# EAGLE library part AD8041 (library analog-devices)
160 MHz Rail-to-Rail Amplifier with Disable Source: http://www.analog.com/static/imported-files/data_sheets/AD8041.pdf
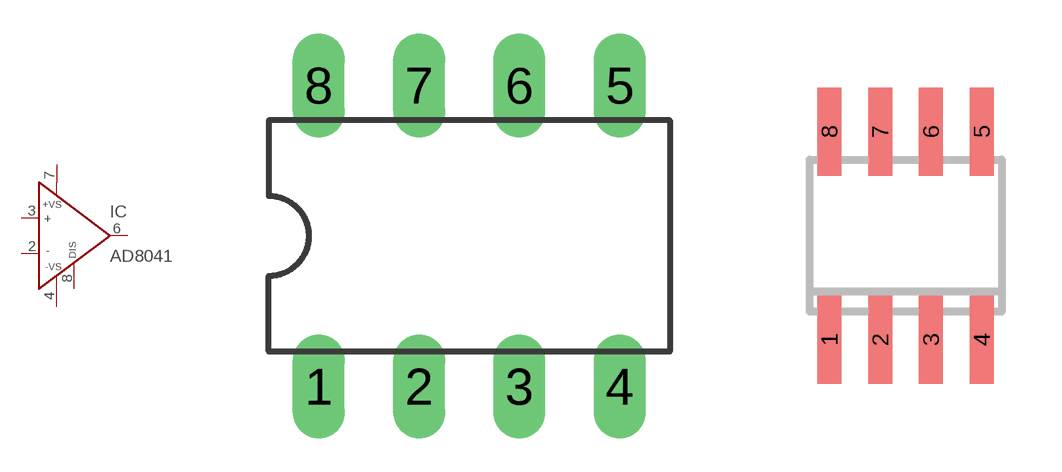
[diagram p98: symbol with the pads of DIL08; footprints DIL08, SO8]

Designator prefix IC

## AD8041N (MPN: AD8041ANZ; OC_FARNELL: 1438577; OC_NEWARK: 15P0923)  [DIL08]
2  IN-  in
3  IN+  in
4  -VS  in
6  OUT  out
7  +VS  in
8  DISABLE  pas

## AD8041R (MF: ALTERA CORPORATION; MPN: AD8041ARZ; OC_FARNELL: 1464831; OC_NEWARK: 88H0130)  [SO8]
Pads as for DIL08

## AD8041Q (MPN: AD8041ANZ; OC_FARNELL: 1438577; OC_NEWARK: 15P0923)  [DIL08]
Pads as for DIL08

## Footprint DIL08 (pad centres in mm)
Dual In Line Package
drill 0.813 long: 1 -3.81,-3.81; 2 -1.27,-3.81; 3 1.27,-3.81; 4 3.81,-3.81; 5 3.81,3.81; 6 1.27,3.81; 7 -1.27,3.81; 8 -3.81,3.81

## Footprint SO8 (pad centres in mm)
8-Lead Small Outline IC (SO-8) Source: http://www.analog.com/UploadedFiles/Data_Sheets/703465986AD8611_2_0.pdf
smd 0.6 x 2.2: 1 -1.905,-2.6; 2 -0.635,-2.6; 3 0.635,-2.6; 4 1.905,-2.6; 5 1.905,2.6; 6 0.635,2.6; 7 -0.635,2.6; 8 -1.905,2.6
